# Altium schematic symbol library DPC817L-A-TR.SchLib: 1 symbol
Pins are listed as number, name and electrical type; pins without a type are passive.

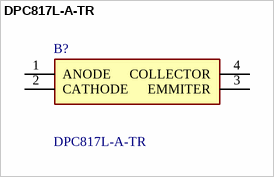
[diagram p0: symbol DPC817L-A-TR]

## DPC817L-A-TR
designator B?
Transistor Output Optocouplers Photo Coupler SLM-4 T&R 2K; Manufacturer_Name: Diodes Incorporated; Geometry.Height: 4.1mm
footprint SOP254P1180X410-4N
pins: 1 ANODE, 2 CATHODE, 3 EMMITER, 4 COLLECTOR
